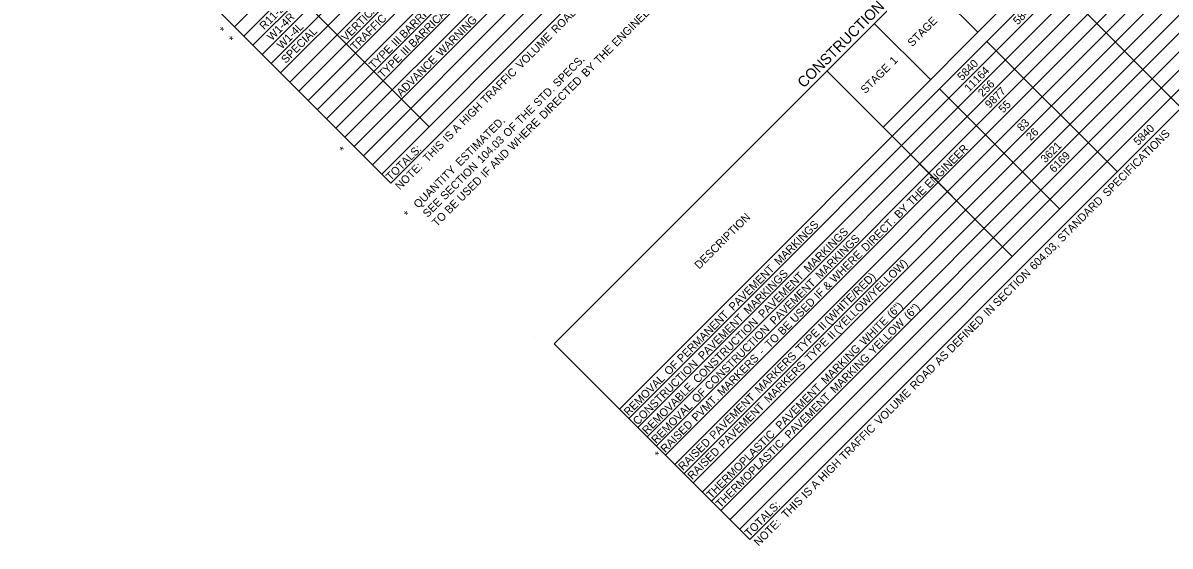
# Model space of a CAD drawing. Extents: x 1675667 to 1681231, y 227227 to 232694.
# Drawn here: x 1675684 to 1676544, y 227227 to 227619 of the extents above; entities that cross this region are included whole.
import ezdxf

# ---------------------------------------------------------------- set-up
doc = ezdxf.new("R2010")
doc.units = 0
doc.layers.add('Default', color=7, linetype='Continuous')

msp = doc.modelspace()

# ---------------------------------------------------------------- linework, layer by layer
at = {"layer": 'Default'}
for p, q in [((1675842.83, 227615.74), (1676477.38, 228250.44)), ((1675849.73, 227608.85), (1676484.27, 228243.55)), ((1675856.62, 227601.95), (1676491.17, 228236.65)), ((1675863.52, 227595.06), (1676498.06, 228229.76)), ((1675870.41, 227588.17), (1676504.96, 228222.86)), ((1675877.31, 227581.27), (1676511.85, 228215.97)), ((1675884.2, 227574.38), (1676518.75, 228209.08)), ((1675891.1, 227567.49), (1676525.64, 228202.18)), ((1675898, 227560.59), (1676532.54, 228195.29)), ((1675904.89, 227553.7), (1676539.43, 228188.4)), ((1675911.79, 227546.81), (1676546.33, 228181.5)), ((1675918.68, 227539.91), (1676553.22, 228174.61)), ((1675925.58, 227533.02), (1676560.12, 228167.72)), ((1675932.47, 227526.13), (1676567.01, 228160.82)), ((1675939.37, 227519.23), (1676573.91, 228153.93)), ((1675946.26, 227512.34), (1676580.8, 228147.04)), ((1675953.16, 227505.45), (1676587.7, 228140.14)), ((1675960.05, 227498.55), (1676594.59, 228133.25)), ((1676082.41, 227378.3), (1676781.4, 228077.46)), ((1676328.86, 227540.69), (1676823.46, 228035.41)), ((1676131.36, 227329.35), (1676830.36, 228028.52)), ((1676138.26, 227322.46), (1676837.25, 228021.63)), ((1676145.15, 227315.57), (1676844.15, 228014.73)), ((1676152.05, 227308.67), (1676851.04, 228007.84)), ((1676158.94, 227301.78), (1676857.94, 228000.95)), ((1676165.84, 227294.89), (1676864.83, 227994.05)), ((1676172.73, 227287.99), (1676871.73, 227987.16)), ((1676179.63, 227281.1), (1676878.62, 227980.27)), ((1676186.52, 227274.21), (1676885.52, 227973.37)), ((1676193.42, 227267.31), (1676892.41, 227966.48)), ((1676200.31, 227260.42), (1676899.31, 227959.59)), ((1676207.21, 227253.53), (1676906.2, 227952.69)), ((1676214.1, 227246.63), (1676913.1, 227945.8)), ((1676221.34, 227239.39), (1676920.34, 227938.56)), ((1676228.93, 227231.81), (1676927.92, 227930.98)), ((1675988.66, 227540.96), (1675719.75, 227809.8)), ((1675960.05, 227498.55), (1675684.25, 227774.29)), ((1675960.05, 227498.55), (1675684.25, 227774.29)), ((1675988.66, 227540.96), (1675761.12, 227768.44)), ((1676399.86, 227611.71), (1676357.8, 227653.76)), ((1676552.23, 227555.19), (1676454.66, 227652.73)), ((1676552.23, 227555.19), (1676454.66, 227652.73)), ((1676364.36, 227576.2), (1676322.3, 227618.25)), ((1676504.32, 227507.27), (1676406.75, 227604.81)), ((1676504.32, 227507.27), (1676406.75, 227604.81)), ((1676425.73, 227443.83), (1676286.8, 227582.74)), ((1676461.23, 227479.34), (1676371.25, 227569.3)), ((1676461.23, 227479.34), (1676371.25, 227569.3)), ((1676425.73, 227443.83), (1676335.75, 227533.79)), ((1676067.58, 227382.78), (1676067.58, 227382.78)), ((1676228.93, 227231.81), (1676082.41, 227378.3)), ((1676228.93, 227231.81), (1676082.41, 227378.3))]:
    msp.add_line(p, q, dxfattribs=at)

# ---------------------------------------------------------------- texts
for s, height, p in [(' BARRICADE-RT.', 6, (1675968.35, 227605.08)), (' BARRICADE-LT.', 6, (1675975.24, 227598.19)), ('R11-2', 6, (1675865.14, 227613.12)), ('VERTICAL', 6, (1675926.44, 227604.53)), (' ROAD', 6, (1676082.19, 227608.63)), (' ENGINEER.', 6, (1676127.57, 227598.86)), ('CONSTRUCTION', 8, (1676269.51, 227569.45)), ('5840', 6, (1676429.83, 227616.76)), ('W1-4R', 6, (1675870.77, 227604.96)), ('TRAFFIC', 6, (1675933.34, 227597.64)), (' WARNING', 6, (1675996.16, 227591.52)), ('STAGE', 6, (1676350.81, 227600.47)), ('*', 6, (1675835.44, 227610.04)), ('W1-4L', 6, (1675878.22, 227598.63)), ('SPECIAL', 6, (1675881.32, 227587.94)), (' VOLUME', 6, (1676055.83, 227582.26)), ('*', 6, (1675842.33, 227603.15)), (' III', 6, (1675962.3, 227599.03)), ('TYPE', 6, (1675947.13, 227583.85)), ('TYPE', 6, (1675954.02, 227576.96)), ('ADVANCE', 6, (1675967.81, 227563.17)), (' III', 6, (1675969.19, 227592.13)), (' THE', 6, (1676114.39, 227585.67)), (' SPECS.', 6, (1676083.45, 227568.52)), (' BY', 6, (1676104.88, 227576.16)), ('STAGE', 6, (1676315.64, 227565.29)), (' 1', 6, (1676335.77, 227585.42)), ('5840', 6, (1676388.13, 227575.04)), ('11164', 6, (1676393.38, 227566.5)), (' TRAFFIC', 6, (1676029.4, 227555.82)), (' DIRECTED', 6, (1676073.25, 227544.53)), (' STD.', 6, (1676068.82, 227553.88)), ('256', 6, (1676403.56, 227562.89)), ('9877', 6, (1676408.8, 227554.35)), ('55', 6, (1676418.98, 227550.74)), (' HIGH', 6, (1676013.41, 227539.83)), (' THE', 6, (1676055.63, 227540.69)), (' ESTIMATED.', 6, (1676010.5, 227509.34)), (' OF', 6, (1676046.03, 227531.08)), (' WHERE', 6, (1676049.86, 227521.13)), ('83', 6, (1676432.78, 227536.97)), (' IS', 6, (1676000.87, 227527.28)), (' A', 6, (1676007.8, 227534.22)), ('26', 6, (1676439.68, 227530.08)), (' SPECIFICATIONS', 6, (1676495.54, 227486.39)), ('5840', 6, (1676520.16, 227526.46)), ('*', 6, (1675925.07, 227520.42)), ('TOTALS:', 6, (1675959.89, 227500.09)), ('  THIS', 6, (1675984.38, 227510.8)), (' 104.03', 6, (1676026.53, 227511.58)), (' ENGINEER', 6, (1676362.09, 227492.88)), ('3621', 6, (1676450.58, 227513.4)), (' AND', 6, (1676036.01, 227507.28)), ('6169', 6, (1676457.07, 227506.1)), ('NOTE:', 6, (1675966.79, 227493.2)), ('QUANTITY', 6, (1675980.58, 227479.41)), (' SECTION', 6, (1675999.02, 227484.07)), (' IF', 6, (1676029.37, 227500.64)), (' USED', 6, (1676011.57, 227482.83)), (' THE', 6, (1676348.9, 227479.69)), ('SEE', 6, (1675987.47, 227472.52)), (' BE', 6, (1676002.33, 227473.59)), (' BY', 6, (1676339.39, 227470.18)), (' STANDARD', 6, (1676461.6, 227452.45)), ('*', 6, (1675973.34, 227472.17)), ('TO', 6, (1675994.37, 227465.62)), ('DESCRIPTION', 6, (1676191.18, 227433.9)), (' MARKINGS', 6, (1676249.36, 227435.29)), (' DIRECT.', 6, (1676314.55, 227445.34)), (' MARKINGS', 6, (1676271.51, 227429.87)), (' MARKINGS', 6, (1676280.21, 227424.78)), (' WHERE', 6, (1676291.16, 227421.94)), (' 604.03,', 6, (1676440.71, 227431.56)), (' (YELLOW/YELLOW)', 6, (1676293.65, 227384.01)), (' PAVEMENT', 6, (1676215.22, 227401.14)), (' MARKINGS', 6, (1676226.39, 227398.53)), (' PAVEMENT', 6, (1676237.38, 227395.72)), (' (WHITE/RED)', 6, (1676286.75, 227390.9)), (' SECTION', 6, (1676413.21, 227404.04)), (' PAVEMENT', 6, (1676246.08, 227390.63)), (' &', 6, (1676285.7, 227416.47)), (' IF', 6, (1676279.05, 227409.83)), (' USED', 6, (1676261.25, 227392.02)), (' (6")', 6, (1676333.81, 227395.65)), (' (6")', 6, (1676346.56, 227394.61)), (' IN', 6, (1676406.12, 227396.95)), (' PERMANENT', 6, (1676176.48, 227362.39)), (' CONSTRUCTION', 6, (1676188.47, 227346.8)), (' PAVEMENT', 6, (1676192.26, 227364.38)), (' WHITE', 6, (1676313.38, 227375.22)), (' YELLOW', 6, (1676320.28, 227368.32)), (' DEFINED', 6, (1676378.77, 227369.6)), (' CONSTRUCTION', 6, (1676197.17, 227341.71)), (' BE', 6, (1676252.02, 227382.78)), (' TYPE', 6, (1676265.53, 227369.68)), (' II', 6, (1676282.35, 227386.5)), (' II', 6, (1676289.24, 227379.6)), ('  TO', 6, (1676240.76, 227371.52)), (' TYPE', 6, (1676272.43, 227362.78)), (' MARKERS', 6, (1676234.88, 227339.02)), (' -', 6, (1676237.32, 227368.09)), (' MARKING', 6, (1676284.45, 227346.27)), (' AS', 6, (1676369.53, 227360.35)), ('CONSTRUCTION', 6, (1676144.99, 227317.1)), (' OF', 6, (1676166.87, 227352.78)), (' MARKERS', 6, (1676206.67, 227337.43)), (' MARKERS', 6, (1676241.78, 227332.13)), (' MARKING', 6, (1676291.34, 227339.38)), (' ROAD', 6, (1676351.07, 227341.89)), ('REMOVAL', 6, (1676138.1, 227324)), ('REMOVABLE', 6, (1676151.89, 227310.21)), (' OF', 6, (1676187.56, 227332.1)), (' PAVEMENT', 6, (1676250.31, 227312.12)), (' VOLUME', 6, (1676324.71, 227315.52)), (' PVMT.', 6, (1676187.43, 227318.18)), (' PAVEMENT', 6, (1676200.74, 227304.87)), (' PAVEMENT', 6, (1676257.2, 227305.23)), ('REMOVAL', 6, (1676158.78, 227303.32)), (' PAVEMENT', 6, (1676207.64, 227297.98)), ('RAISED', 6, (1676165.68, 227296.42)), ('THERMOPLASTIC', 6, (1676200.15, 227261.96)), (' TRAFFIC', 6, (1676298.27, 227289.08)), ('RAISED', 6, (1676178.99, 227283.11)), ('THERMOPLASTIC', 6, (1676207.05, 227255.06)), ('*', 6, (1676161.35, 227292.1)), ('RAISED', 6, (1676185.89, 227276.22)), (' HIGH', 6, (1676282.29, 227273.09)), (' IS', 6, (1676269.74, 227260.54)), (' A', 6, (1676276.68, 227267.48)), ('TOTALS:', 6, (1676228.77, 227233.35)), ('  THIS', 6, (1676253.26, 227244.06)), ('NOTE:', 6, (1676235.66, 227226.46))]:
    msp.add_text(s, height=height, rotation=45.00703, dxfattribs=at).set_placement(p)

doc.saveas('drawing.dxf')
